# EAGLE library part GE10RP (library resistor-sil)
SIL RESISTOR
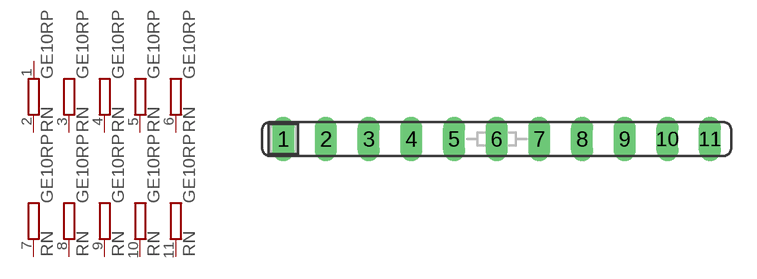
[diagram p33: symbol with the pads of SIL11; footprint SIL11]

Designator prefix RN; gates A=R-PV B=R-PV1 C=R-PV1 D=R-PV1 E=R-PV1 F=R-PV1 G=R-PV1 H=R-PV1 I=R-PV1 J=R-PV1

## GE10RP (OC_FARNELL: unknown; OC_NEWARK: unknown)  [SIL11]
1  A:1  pas
2  A:2  pas
3  B:2  pas
4  C:2  pas
5  D:2  pas
6  E:2  pas
7  F:2  pas
8  G:2  pas
9  H:2  pas
10  I:2  pas
11  J:2  pas

## Footprint SIL11 (pad centres in mm)
Single In Line
drill 0.813 long: 1 -12.7,0; 2 -10.16,0; 3 -7.62,0; 4 -5.08,0; 5 -2.54,0; 6 0,0; 7 2.54,0; 8 5.08,0; 9 7.62,0; 10 10.16,0; 11 12.7,0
